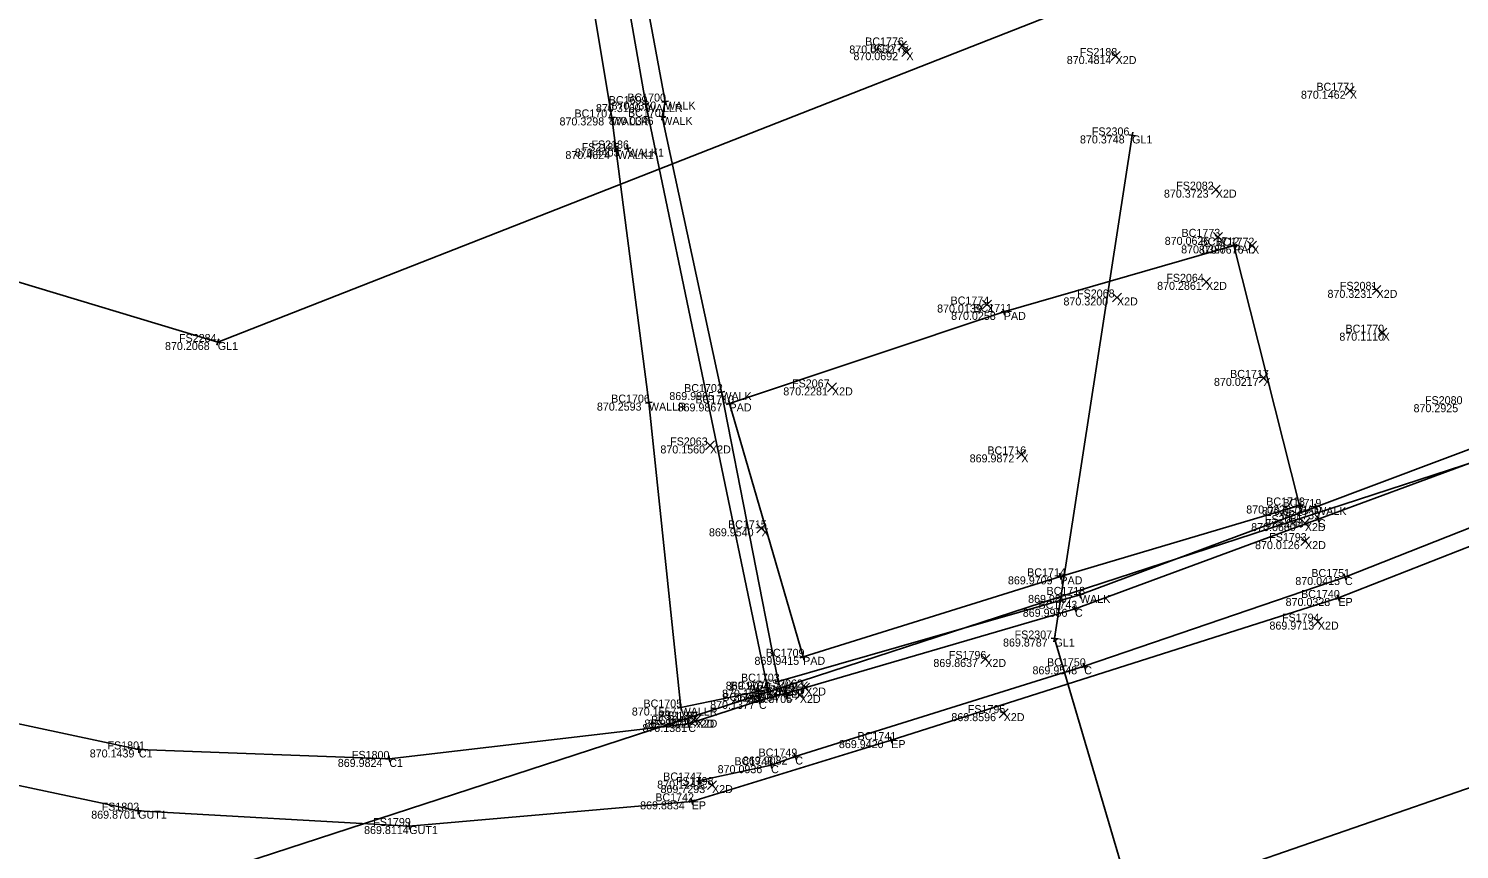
# Model space of a CAD drawing. Extents: x 1479425 to 1480294, y 379351 to 380102.
# Drawn here: x 1479659.17 to 1479669.9, y 379941.22 to 379947.37 of the extents above; entities that cross this region are included whole.
import ezdxf

# ---------------------------------------------------------------- set-up
doc = ezdxf.new("R2010")
doc.units = 0
for name, color, linetype in [('PV_X_Curb', 7, 'Continuous'), ('PV_X_Walk', 7, 'Continuous'), ('RD_X_Concrete_Pad', 7, 'Continuous'), ('RD_X_Wall', 7, 'Continuous'), ('SV_X_Random_Point', 7, 'Continuous'), ('SV_X_Shot_Marker', 7, 'Continuous'), ('SV_X_Text_Comment', 7, 'Continuous'), ('SV_X_Text_Elevation', 7, 'Continuous'), ('SV_X_Text_Name', 7, 'Continuous'), ('UT_X_Gas', 7, 'Continuous'), ('UT_X_Sanitary_Line', 7, 'Continuous'), ('UT_X_Telecom', 7, 'Continuous')]:
    doc.layers.add(name, color=color, linetype=linetype)

msp = doc.modelspace()

# ---------------------------------------------------------------- linework, layer by layer
at = {"layer": 'PV_X_Curb'}
for points in [[(1479791.59, 380003.464), (1479772.982, 379994.381), (1479762.438, 379989.23), (1479737.891, 379977.225), (1479720.638, 379968.611), (1479698.71, 379957.883), (1479682.413, 379949.79), (1479678.756, 379947.988), (1479678.525, 379947.942), (1479675.465, 379946.488), (1479673.909, 379945.774), (1479671.056, 379944.49), (1479670.881, 379944.45), (1479668.837, 379943.696), (1479667.016, 379943.025), (1479664.845, 379942.391), (1479664.647, 379942.335), (1479664.117, 379942.162), (1479661.876, 379941.9), (1479659.999, 379941.971), (1479653.935, 379943.268), (1479649.182, 379945.527), (1479644.261, 379948.889)], [(1479791.848, 380002.989), (1479773.254, 379993.873), (1479762.766, 379988.772), (1479738.122, 379976.643), (1479720.845, 379968.214), (1479698.694, 379957.239), (1479682.744, 379949.362), (1479678.802, 379947.48), (1479675.687, 379946.021), (1479671.323, 379944.026), (1479668.99, 379943.106), (1479665.638, 379942.041), (1479664.143, 379941.582), (1479662.026, 379941.397), (1479659.994, 379941.512), (1479654.023, 379942.767), (1479648.758, 379945.101), (1479643.81, 379948.553)], [(1479664.204, 379941.738), (1479664.738, 379941.853), (1479664.919, 379941.918), (1479667.085, 379942.594), (1479669.039, 379943.263), (1479671.07, 379944.064), (1479673.811, 379945.322), (1479675.836, 379946.224), (1479678.71, 379947.573), (1479678.867, 379947.609), (1479682.623, 379949.494)]]:
    msp.add_lwpolyline(points, dxfattribs=at)
at = {"layer": 'PV_X_Walk'}
msp.add_lwpolyline([(1479661.246, 379962.328), (1479661.797, 379958.518), (1479661.797, 379958.436), (1479662.13, 379956.636), (1479662.429, 379954.458), (1479662.418, 379954.306), (1479662.501, 379953.552), (1479662.697, 379953.542), (1479663.251, 379950.555), (1479663.285, 379950.436), (1479663.607, 379948.647), (1479663.944, 379946.826), (1479663.922, 379946.711), (1479664.365, 379944.649), (1479664.791, 379942.479), (1479667.053, 379943.129), (1479668.823, 379943.788), (1479670.732, 379944.506)], dxfattribs=at)
at = {"layer": 'RD_X_Concrete_Pad'}
msp.add_lwpolyline([(1479664.978, 379942.665), (1479664.426, 379944.564), (1479666.482, 379945.25), (1479668.207, 379945.748), (1479668.699, 379943.799), (1479666.906, 379943.268)], close=True, dxfattribs=at)
at = {"layer": 'RD_X_Wall'}
msp.add_lwpolyline([(1479662.541, 379953.508), (1479662.675, 379953.453), (1479663.151, 379950.511), (1479663.798, 379946.807), (1479664.714, 379942.419), (1479664.06, 379942.285), (1479663.822, 379944.57), (1479663.543, 379946.707), (1479662.929, 379950.389)], close=True, dxfattribs=at)
at = {"layer": 'SV_X_Random_Point'}
for p, q in [((1479665.687, 379947.212), (1479665.753, 379947.279)), ((1479665.687, 379947.279), (1479665.753, 379947.212)), ((1479665.718, 379947.163), (1479665.785, 379947.229)), ((1479665.718, 379947.229), (1479665.785, 379947.163)), ((1479667.287, 379947.134), (1479667.353, 379947.201)), ((1479667.287, 379947.201), (1479667.353, 379947.134)), ((1479669.042, 379946.874), (1479669.109, 379946.94)), ((1479669.042, 379946.94), (1479669.109, 379946.874)), ((1479668.038, 379946.133), (1479668.104, 379946.199)), ((1479668.038, 379946.199), (1479668.104, 379946.133)), ((1479668.054, 379945.779), (1479668.121, 379945.845)), ((1479668.054, 379945.845), (1479668.121, 379945.779)), ((1479668.309, 379945.713), (1479668.376, 379945.779)), ((1479668.309, 379945.779), (1479668.376, 379945.713)), ((1479667.965, 379945.441), (1479668.031, 379945.508)), ((1479667.965, 379945.508), (1479668.031, 379945.441)), ((1479667.297, 379945.324), (1479667.363, 379945.391)), ((1479667.297, 379945.391), (1479667.363, 379945.324)), ((1479669.243, 379945.381), (1479669.309, 379945.448)), ((1479669.243, 379945.448), (1479669.309, 379945.381)), ((1479666.322, 379945.272), (1479666.389, 379945.338)), ((1479666.322, 379945.338), (1479666.389, 379945.272)), ((1479669.287, 379945.061), (1479669.354, 379945.127)), ((1479669.287, 379945.127), (1479669.354, 379945.061)), ((1479668.395, 379944.721), (1479668.462, 379944.788)), ((1479668.395, 379944.788), (1479668.462, 379944.721)), ((1479665.161, 379944.65), (1479665.227, 379944.717)), ((1479665.161, 379944.717), (1479665.227, 379944.65)), ((1479664.247, 379944.216), (1479664.313, 379944.283)), ((1479664.247, 379944.283), (1479664.313, 379944.216)), ((1479666.579, 379944.148), (1479666.646, 379944.215)), ((1479666.579, 379944.215), (1479666.646, 379944.148)), ((1479668.705, 379943.634), (1479668.771, 379943.7)), ((1479668.705, 379943.7), (1479668.771, 379943.634)), ((1479664.632, 379943.594), (1479664.699, 379943.661)), ((1479664.632, 379943.661), (1479664.699, 379943.594)), ((1479668.707, 379943.498), (1479668.773, 379943.565)), ((1479668.707, 379943.565), (1479668.773, 379943.498)), ((1479668.803, 379942.895), (1479668.869, 379942.962)), ((1479668.803, 379942.962), (1479668.869, 379942.895)), ((1479666.31, 379942.615), (1479666.376, 379942.682)), ((1479666.31, 379942.682), (1479666.376, 379942.615)), ((1479664.92, 379942.346), (1479664.986, 379942.413)), ((1479664.92, 379942.413), (1479664.986, 379942.346)), ((1479664.96, 379942.401), (1479665.026, 379942.468)), ((1479664.96, 379942.468), (1479665.026, 379942.401)), ((1479664.123, 379942.16), (1479664.189, 379942.227)), ((1479664.123, 379942.227), (1479664.189, 379942.16)), ((1479664.146, 379942.162), (1479664.212, 379942.228)), ((1479664.146, 379942.228), (1479664.212, 379942.162)), ((1479666.448, 379942.209), (1479666.514, 379942.276)), ((1479666.448, 379942.276), (1479666.514, 379942.209)), ((1479664.262, 379941.67), (1479664.328, 379941.737)), ((1479664.262, 379941.737), (1479664.328, 379941.67))]:
    msp.add_line(p, q, dxfattribs=at)
at = {"layer": 'SV_X_Shot_Marker'}
for p, q in [((1479663.822, 379946.812), (1479663.773, 379946.803)), ((1479663.793, 379946.832), (1479663.802, 379946.783)), ((1479663.798, 379946.807), (1479663.798, 379946.807)), ((1479663.969, 379946.83), (1479663.92, 379946.821)), ((1479663.94, 379946.85), (1479663.949, 379946.801)), ((1479663.944, 379946.826), (1479663.944, 379946.826)), ((1479663.519, 379946.703), (1479663.568, 379946.71)), ((1479663.547, 379946.682), (1479663.54, 379946.731)), ((1479663.543, 379946.707), (1479663.543, 379946.707)), ((1479663.947, 379946.706), (1479663.898, 379946.716)), ((1479663.927, 379946.735), (1479663.918, 379946.686)), ((1479663.922, 379946.711), (1479663.922, 379946.711)), ((1479667.469, 379946.568), (1479667.419, 379946.576)), ((1479667.448, 379946.597), (1479667.44, 379946.547)), ((1479667.444, 379946.572), (1479667.444, 379946.572)), ((1479663.583, 379946.479), (1479663.589, 379946.43)), ((1479663.639, 379946.468), (1479663.687, 379946.48)), ((1479663.657, 379946.498), (1479663.669, 379946.449)), ((1479663.663, 379946.474), (1479663.663, 379946.474)), ((1479663.611, 379946.458), (1479663.561, 379946.451)), ((1479663.586, 379946.455), (1479663.586, 379946.455)), ((1479668.183, 379945.741), (1479668.231, 379945.755)), ((1479668.2, 379945.772), (1479668.214, 379945.724)), ((1479668.207, 379945.748), (1479668.207, 379945.748)), ((1479666.458, 379945.242), (1479666.505, 379945.258)), ((1479666.474, 379945.273), (1479666.49, 379945.226)), ((1479666.482, 379945.25), (1479666.482, 379945.25)), ((1479660.567, 379945.031), (1479660.615, 379945.017)), ((1479660.598, 379945.048), (1479660.584, 379945)), ((1479660.591, 379945.024), (1479660.591, 379945.024)), ((1479664.39, 379944.654), (1479664.341, 379944.643)), ((1479664.36, 379944.673), (1479664.37, 379944.624)), ((1479664.365, 379944.649), (1479664.365, 379944.649)), ((1479663.797, 379944.567), (1479663.847, 379944.573)), ((1479663.825, 379944.545), (1479663.82, 379944.595)), ((1479663.822, 379944.57), (1479663.822, 379944.57)), ((1479664.402, 379944.557), (1479664.45, 379944.571)), ((1479664.433, 379944.54), (1479664.419, 379944.588)), ((1479664.426, 379944.564), (1479664.426, 379944.564)), ((1479668.724, 379943.805), (1479668.675, 379943.793)), ((1479668.693, 379943.823), (1479668.706, 379943.775)), ((1479668.699, 379943.799), (1479668.699, 379943.799)), ((1479668.799, 379943.779), (1479668.846, 379943.797)), ((1479668.814, 379943.811), (1479668.832, 379943.764)), ((1479668.823, 379943.788), (1479668.823, 379943.788)), ((1479668.86, 379943.705), (1479668.813, 379943.687)), ((1479668.846, 379943.673), (1479668.828, 379943.72)), ((1479668.837, 379943.696), (1479668.837, 379943.696)), ((1479666.93, 379943.275), (1479666.882, 379943.261)), ((1479666.913, 379943.244), (1479666.899, 379943.292)), ((1479666.906, 379943.268), (1479666.906, 379943.268)), ((1479669.015, 379943.254), (1479669.063, 379943.271)), ((1479669.031, 379943.286), (1479669.047, 379943.239)), ((1479669.039, 379943.263), (1479669.039, 379943.263)), ((1479667.046, 379943.153), (1479667.06, 379943.105)), ((1479667.04, 379943.033), (1479666.993, 379943.016)), ((1479667.025, 379943.001), (1479667.008, 379943.048)), ((1479667.029, 379943.122), (1479667.077, 379943.136)), ((1479667.053, 379943.129), (1479667.053, 379943.129)), ((1479669.013, 379943.115), (1479668.967, 379943.097)), ((1479668.999, 379943.082), (1479668.981, 379943.129)), ((1479668.99, 379943.106), (1479668.99, 379943.106)), ((1479667.016, 379943.025), (1479667.016, 379943.025)), ((1479666.866, 379942.827), (1479666.858, 379942.778)), ((1479666.887, 379942.799), (1479666.837, 379942.806)), ((1479666.862, 379942.802), (1479666.862, 379942.802)), ((1479664.954, 379942.658), (1479665.002, 379942.672)), ((1479664.985, 379942.641), (1479664.971, 379942.689)), ((1479664.978, 379942.665), (1479664.978, 379942.665)), ((1479667.062, 379942.586), (1479667.109, 379942.601)), ((1479667.078, 379942.617), (1479667.093, 379942.57)), ((1479664.787, 379942.503), (1479664.796, 379942.454)), ((1479667.085, 379942.594), (1479667.085, 379942.594)), ((1479664.738, 379942.425), (1479664.689, 379942.414)), ((1479664.708, 379942.444), (1479664.719, 379942.395)), ((1479664.714, 379942.419), (1479664.714, 379942.419)), ((1479664.816, 379942.484), (1479664.767, 379942.474)), ((1479664.791, 379942.479), (1479664.791, 379942.479)), ((1479664.869, 379942.398), (1479664.821, 379942.384)), ((1479664.852, 379942.367), (1479664.838, 379942.415)), ((1479664.845, 379942.391), (1479664.845, 379942.391)), ((1479664.085, 379942.29), (1479664.036, 379942.28)), ((1479664.065, 379942.261), (1479664.055, 379942.31)), ((1479664.06, 379942.285), (1479664.06, 379942.285)), ((1479664.671, 379942.341), (1479664.623, 379942.328)), ((1479664.654, 379942.311), (1479664.64, 379942.359)), ((1479664.647, 379942.335), (1479664.647, 379942.335)), ((1479664.112, 379942.186), (1479664.122, 379942.137)), ((1479664.141, 379942.167), (1479664.093, 379942.157)), ((1479664.117, 379942.162), (1479664.117, 379942.162)), ((1479665.646, 379942.017), (1479665.631, 379942.065)), ((1479660.024, 379941.97), (1479659.974, 379941.972)), ((1479659.998, 379941.946), (1479660, 379941.996)), ((1479659.999, 379941.971), (1479659.999, 379941.971)), ((1479665.662, 379942.049), (1479665.614, 379942.034)), ((1479665.638, 379942.041), (1479665.638, 379942.041)), ((1479661.901, 379941.903), (1479661.851, 379941.898)), ((1479661.879, 379941.876), (1479661.873, 379941.925)), ((1479661.876, 379941.9), (1479661.876, 379941.9)), ((1479664.713, 379941.848), (1479664.762, 379941.859)), ((1479664.732, 379941.878), (1479664.743, 379941.829)), ((1479664.738, 379941.853), (1479664.738, 379941.853)), ((1479664.896, 379941.909), (1479664.943, 379941.926)), ((1479664.911, 379941.941), (1479664.928, 379941.894)), ((1479664.919, 379941.918), (1479664.919, 379941.918)), ((1479664.179, 379941.733), (1479664.228, 379941.743)), ((1479664.199, 379941.762), (1479664.209, 379941.713)), ((1479664.204, 379941.738), (1479664.204, 379941.738)), ((1479659.993, 379941.487), (1479659.995, 379941.537)), ((1479664.167, 379941.59), (1479664.12, 379941.575)), ((1479664.151, 379941.558), (1479664.136, 379941.606)), ((1479664.143, 379941.582), (1479664.143, 379941.582)), ((1479660.019, 379941.51), (1479659.969, 379941.513)), ((1479659.994, 379941.512), (1479659.994, 379941.512)), ((1479662.028, 379941.372), (1479662.024, 379941.421)), ((1479662.051, 379941.399), (1479662.001, 379941.394)), ((1479662.026, 379941.397), (1479662.026, 379941.397))]:
    msp.add_line(p, q, dxfattribs=at)
at = {"layer": 'UT_X_Gas'}
for points in [[(1479646.785, 379955.438), (1479652.981, 379949.433), (1479657.465, 379945.964), (1479660.591, 379945.024), (1479670.935, 379949.08), (1479679.157, 379953.065), (1479685.442, 379955.742), (1479689.462, 379958.127), (1479696.956, 379963.013), (1479705.088, 379967.488), (1479713.465, 379971.226), (1479723.024, 379975.676), (1479732.065, 379980.116), (1479742.535, 379985.018), (1479753.798, 379990.643), (1479767.065, 379997.456), (1479775.982, 380001.733), (1479789.966, 380007.789)], [(1479667.444, 379946.572), (1479666.862, 379942.802), (1479667.538, 379940.507), (1479675.403, 379934.504), (1479682.743, 379926.326), (1479692.421, 379916.824), (1479702.659, 379906.694), (1479713.881, 379895.567), (1479724.225, 379885.781), (1479733.117, 379877.795), (1479742.697, 379869.326), (1479754.816, 379857.131), (1479762.869, 379849.318), (1479772.436, 379840.641), (1479780.346, 379832.715), (1479784.901, 379828.191), (1479795.906, 379818.324), (1479806.128, 379806.719), (1479816.671, 379794.927)]]:
    msp.add_lwpolyline(points, dxfattribs=at)
at = {"layer": 'UT_X_Sanitary_Line'}
msp.add_lwpolyline([(1479514.622, 379866.87), (1479542.109, 379880.195), (1479565.169, 379891.725), (1479588.442, 379902.577), (1479600.276, 379909.045), (1479620.421, 379921.063), (1479621.963, 379921.485), (1479624.647, 379923.417), (1479645.234, 379932.512), (1479652.585, 379935.616), (1479664.157, 379939.675), (1479679.103, 379944.837), (1479710.112, 379956.448), (1479736.037, 379968.233), (1479798.147, 379991.168), (1479820.4, 379999.933), (1479823.042, 380000.22)], dxfattribs=at)
at = {"layer": 'UT_X_Telecom'}
msp.add_lwpolyline([(1479654.736, 379936.58), (1479659.767, 379940.788), (1479670.95, 379944.434), (1479693.183, 379956.652)], dxfattribs=at)

# ---------------------------------------------------------------- texts
at = {"layer": 'SV_X_Text_Comment'}
for s, p in [('X', (1479665.72, 379947.186)), ('X', (1479665.752, 379947.136)), ('X2D', (1479667.32, 379947.107)), ('X', (1479669.076, 379946.847)), ('WALLR', (1479663.798, 379946.747)), ('WALK', (1479663.944, 379946.766)), ('WALLR', (1479663.543, 379946.647)), ('WALK', (1479663.922, 379946.651)), ('GL1', (1479667.444, 379946.512)), ('WALK1', (1479663.663, 379946.414)), ('WALK1', (1479663.586, 379946.395)), ('X2D', (1479668.071, 379946.106)), ('X', (1479668.087, 379945.752)), ('PAD', (1479668.207, 379945.688)), ('X', (1479668.343, 379945.686)), ('X2D', (1479667.998, 379945.415)), ('X2D', (1479669.276, 379945.355)), ('X', (1479666.355, 379945.245)), ('X2D', (1479667.33, 379945.298)), ('PAD', (1479666.482, 379945.19)), ('X', (1479669.321, 379945.034)), ('GL1', (1479660.591, 379944.964)), ('X', (1479668.428, 379944.695)), ('WALK', (1479664.365, 379944.589)), ('X2D', (1479665.194, 379944.624)), ('WALLR', (1479663.822, 379944.51)), ('PAD', (1479664.426, 379944.504)), ('X2D', (1479664.28, 379944.189)), ('X', (1479666.613, 379944.122)), ('PAD', (1479668.699, 379943.739)), ('WALK', (1479668.823, 379943.728)), ('C', (1479668.837, 379943.636)), ('X', (1479664.666, 379943.568)), ('X2D', (1479668.738, 379943.607)), ('X2D', (1479668.74, 379943.472)), ('PAD', (1479666.906, 379943.208)), ('C', (1479669.039, 379943.203)), ('WALK', (1479667.053, 379943.069)), ('EP', (1479668.99, 379943.046)), ('C', (1479667.016, 379942.965)), ('X2D', (1479668.836, 379942.869)), ('GL1', (1479666.862, 379942.742)), ('PAD', (1479664.978, 379942.605)), ('X2D', (1479666.343, 379942.589)), ('C', (1479667.085, 379942.534)), ('WALLR', (1479664.714, 379942.359)), ('WALK', (1479664.791, 379942.419)), ('C', (1479664.845, 379942.331)), ('X2D', (1479664.993, 379942.375)), ('WALLR', (1479664.06, 379942.225)), ('C', (1479664.647, 379942.275)), ('X2D', (1479664.953, 379942.319)), ('X2D', (1479664.156, 379942.134)), ('X2D', (1479664.179, 379942.135)), ('X2D', (1479666.481, 379942.183)), ('C', (1479664.117, 379942.102)), ('C1', (1479659.999, 379941.911)), ('EP', (1479665.638, 379941.981)), ('C1', (1479661.876, 379941.84)), ('C', (1479664.738, 379941.793)), ('C', (1479664.919, 379941.858)), ('C', (1479664.204, 379941.678)), ('X2D', (1479664.295, 379941.644)), ('EP', (1479664.143, 379941.522)), ('GUT1', (1479659.994, 379941.452)), ('GUT1', (1479662.026, 379941.337))]:
    msp.add_text(s, height=0.06, dxfattribs=at).set_placement(p)
at = {"layer": 'SV_X_Text_Elevation'}
for s, p in [('870.0652', (1479665.324, 379947.186)), ('870.0692', (1479665.355, 379947.136)), ('870.4814', (1479666.954, 379947.107)), ('870.1462', (1479668.709, 379946.847)), ('870.3160', (1479663.425, 379946.747)), ('870.0360', (1479663.542, 379946.766)), ('870.3298', (1479663.152, 379946.647)), ('870.0346', (1479663.522, 379946.651)), ('870.3748', (1479667.053, 379946.512)), ('870.4403', (1479663.267, 379946.414)), ('870.4624', (1479663.196, 379946.395)), ('870.3723', (1479667.682, 379946.106)), ('870.0626', (1479667.688, 379945.752)), ('870.0387', (1479667.811, 379945.688)), ('870.0676', (1479667.944, 379945.686)), ('870.2861', (1479667.631, 379945.415)), ('870.3231', (1479668.908, 379945.355)), ('870.0139', (1479665.982, 379945.245)), ('870.3200', (1479666.929, 379945.298)), ('870.0258', (1479666.087, 379945.19)), ('870.1110', (1479668.997, 379945.034)), ('870.2068', (1479660.195, 379944.964)), ('870.0217', (1479668.057, 379944.695)), ('869.9965', (1479663.975, 379944.589)), ('870.2281', (1479664.829, 379944.624)), ('870.2593', (1479663.432, 379944.51)), ('869.9867', (1479664.037, 379944.504)), ('870.2925', (1479669.553, 379944.498)), ('870.1560', (1479663.908, 379944.189)), ('869.9872', (1479666.226, 379944.122)), ('870.0320', (1479668.299, 379943.739)), ('870.0500', (1479668.417, 379943.728)), ('870.0484', (1479668.441, 379943.636)), ('869.9540', (1479664.272, 379943.568)), ('870.0680', (1479668.336, 379943.607)), ('870.0126', (1479668.365, 379943.472)), ('869.9709', (1479666.513, 379943.208)), ('870.0415', (1479668.667, 379943.203)), ('869.9897', (1479666.664, 379943.069)), ('870.0328', (1479668.594, 379943.046)), ('869.9956', (1479666.624, 379942.965)), ('869.9713', (1479668.473, 379942.869)), ('869.8787', (1479666.476, 379942.742)), ('869.9415', (1479664.613, 379942.605)), ('869.8637', (1479665.954, 379942.589)), ('869.9548', (1479666.697, 379942.534)), ('870.1451', (1479664.37, 379942.359)), ('869.9079', (1479664.398, 379942.419)), ('869.8964', (1479664.457, 379942.331)), ('869.8529', (1479664.607, 379942.375)), ('870.1557', (1479663.694, 379942.225)), ('870.1377', (1479664.281, 379942.275)), ('869.8705', (1479664.561, 379942.319)), ('869.8072', (1479663.788, 379942.135)), ('869.8121', (1479663.816, 379942.134)), ('869.8596', (1479666.089, 379942.183)), ('870.1381', (1479663.773, 379942.102)), ('870.1439', (1479659.631, 379941.911)), ('869.9420', (1479665.246, 379941.981)), ('869.9824', (1479661.49, 379941.84)), ('870.0936', (1479664.337, 379941.793)), ('869.9082', (1479664.526, 379941.858)), ('870.1141', (1479663.884, 379941.678)), ('869.7293', (1479663.909, 379941.644)), ('869.8834', (1479663.756, 379941.522)), ('869.8701', (1479659.642, 379941.452)), ('869.8114', (1479661.687, 379941.337))]:
    msp.add_text(s, height=0.06, dxfattribs=at).set_placement(p)
at = {"layer": 'SV_X_Text_Name'}
for s, p in [('BC1776', (1479665.443, 379947.246)), ('BC1775', (1479665.479, 379947.196)), ('FS2188', (1479667.051, 379947.167)), ('BC1771', (1479668.825, 379946.907)), ('BC1699', (1479663.521, 379946.807)), ('BC1700', (1479663.66, 379946.826)), ('BC1707', (1479663.264, 379946.707)), ('BC1701', (1479663.665, 379946.711)), ('FS2306', (1479667.142, 379946.572)), ('FS2185', (1479663.318, 379946.455)), ('FS2186', (1479663.391, 379946.474)), ('FS2082', (1479667.774, 379946.166)), ('BC1773', (1479667.814, 379945.812)), ('BC1712', (1479667.957, 379945.748)), ('BC1772', (1479668.07, 379945.746)), ('FS2064', (1479667.7, 379945.475)), ('FS2068', (1479667.031, 379945.358)), ('FS2081', (1479669.001, 379945.415)), ('BC1774', (1479666.083, 379945.305)), ('BC1711', (1479666.254, 379945.25)), ('FS2284', (1479660.3, 379945.024)), ('BC1770', (1479669.043, 379945.094)), ('BC1717', (1479668.178, 379944.755)), ('BC1702', (1479664.086, 379944.649)), ('FS2067', (1479664.895, 379944.684)), ('BC1706', (1479663.539, 379944.57)), ('BC1710', (1479664.17, 379944.564)), ('FS2080', (1479669.639, 379944.558)), ('FS2063', (1479663.981, 379944.249)), ('BC1716', (1479666.359, 379944.182)), ('BC1713', (1479668.449, 379943.799)), ('BC1719', (1479668.572, 379943.788)), ('BC1715', (1479664.415, 379943.628)), ('FS2065', (1479668.439, 379943.667)), ('BC1739', (1479668.562, 379943.696)), ('FS1793', (1479668.471, 379943.532)), ('BC1714', (1479666.657, 379943.268)), ('BC1751', (1479668.787, 379943.263)), ('BC1718', (1479666.802, 379943.129)), ('BC1740', (1479668.71, 379943.106)), ('BC1743', (1479666.742, 379943.025)), ('FS1794', (1479668.567, 379942.929)), ('FS2307', (1479666.563, 379942.802)), ('BC1709', (1479664.698, 379942.665)), ('FS1796', (1479666.07, 379942.649)), ('BC1750', (1479666.806, 379942.594)), ('BC1703', (1479664.512, 379942.479)), ('FS2062', (1479664.695, 379942.435)), ('BC1745', (1479664.372, 379942.335)), ('BC1704', (1479664.434, 379942.419)), ('BC1744', (1479664.571, 379942.391)), ('FS2066', (1479664.651, 379942.379)), ('BC1705', (1479663.781, 379942.285)), ('FS1795', (1479666.212, 379942.243)), ('BC1746', (1479663.839, 379942.162)), ('FS2187', (1479663.888, 379942.194)), ('FS1797', (1479663.91, 379942.195)), ('BC1741', (1479665.386, 379942.041)), ('FS1801', (1479659.764, 379941.971)), ('FS1800', (1479661.596, 379941.9)), ('BC1749', (1479664.644, 379941.918)), ('BC1748', (1479664.463, 379941.853)), ('BC1747', (1479663.929, 379941.738)), ('FS1798', (1479664.025, 379941.704)), ('BC1742', (1479663.87, 379941.582)), ('FS1802', (1479659.72, 379941.512)), ('FS1799', (1479661.756, 379941.397))]:
    msp.add_text(s, height=0.06, dxfattribs=at).set_placement(p)

doc.saveas('drawing.dxf')
